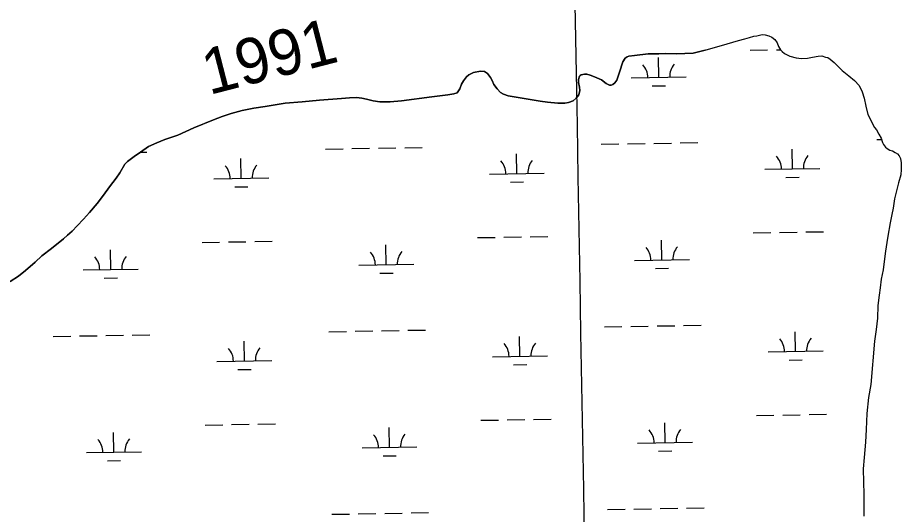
# Model space of a CAD drawing. Extents: x 3892998 to 3931244, y 278583 to 304547.
# Drawn here: x 3917313 to 3918922, y 294371 to 295276 of the extents above; entities that cross this region are included whole.
import ezdxf

# ---------------------------------------------------------------- set-up
doc = ezdxf.new("R2010")
doc.units = 0
for name, color, linetype in [('V-GRID-MAJR', 7, 'Continuous'), ('V-RIVR-IDEN', 7, 'Continuous'), ('V-TOPO-SHOR', 7, 'Continuous'), ('V-WETL-SWMP', 7, 'Continuous')]:
    doc.layers.add(name, color=color, linetype=linetype)

msp = doc.modelspace()

# ---------------------------------------------------------------- linework, layer by layer
at = {"layer": 'V-GRID-MAJR'}
msp.add_spline([(3918519.216, 284383.145), (3918413.491, 290439.973), (3918307.7120000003, 296499.886), (3918201.934, 302559.792), (3918201.88, 302562.882)], degree=3, dxfattribs=at)
at = {"layer": 'V-TOPO-SHOR'}
for points in [[(3918565.202, 295216.348), (3918605.168, 295228.228), (3918615.648, 295231.005), (3918626.123, 295234.174), (3918637.379, 295236.957), (3918645.913, 295239.724), (3918654.0640000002, 295241.712), (3918659.115, 295242.517), (3918664.1610000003, 295243.711), (3918669.205, 295244.905), (3918674.651, 295244.158), (3918680.879, 295242.638), (3918686.722, 295240.338), (3918691.799, 295235.702), (3918696.106, 295229.895), (3918698.864, 295222.916), (3918702.395, 295217.106), (3918705.133, 295214.011), (3918709.819, 295210.151), (3918719.1720000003, 295205.539), (3918730.848, 295202.493), (3918740.572, 295201.381), (3918751.451, 295201.83), (3918760.767, 295203.824), (3918770.862, 295205.82300000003), (3918777.858, 295205.862), (3918784.088, 295203.953), (3918788.757, 295202.813), (3918793.048, 295200.115), (3918800.076, 295193.93700000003), (3918807.5, 295186.982), (3918814.924, 295179.638), (3918826.6410000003, 295169.596), (3918837.182, 295161.105), (3918845.393, 295152.211), (3918851.287, 295140.58400000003), (3918854.846, 295129.332), (3918858.039, 295114.581), (3918861.6210000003, 295099.055), (3918873.8000000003, 295075.413), (3918876.934, 295071.155), (3918881.251, 295063.405), (3918885.5640000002, 295056.434), (3918888.3310000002, 295048.287), (3918889.906, 295044.797), (3918893.8200000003, 295039.767), (3918896.552, 295037.451), (3918901.622, 295034.369), (3918906.292, 295033.228), (3918911.363, 295030.148), (3918915.2600000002, 295027.838), (3918918.781, 295023.969), (3918920.753, 295018.929), (3918921.961, 295011.161), (3918922.416, 294999.115), (3918921.304, 294989.393), (3918917.1070000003, 294974.989), (3918914.0640000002, 294962.924), (3918910.273, 294945.801), (3918907.258, 294928.684), (3918905.38, 294917.012), (3918902.3540000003, 294901.839), (3918897.823, 294877.717), (3918895.9450000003, 294866.048), (3918893.312, 294850.098), (3918891.083, 294831.428), (3918889.224, 294816.261), (3918885.8200000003, 294799.142), (3918883.9620000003, 294783.583), (3918882.093, 294770.359), (3918879.866, 294751.302), (3918879.215, 294728.369), (3918876.608, 294707.756), (3918873.6180000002, 294686.362), (3918866.669, 294607.424), (3918862.9110000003, 294584.085), (3918859.575, 294554.918), (3918858.182, 294525.371), (3918857.144, 294502.434), (3918854.967, 294474.43700000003), (3918853.136, 294453.828), (3918853.269, 294429.734), (3918854.168, 294407.974), (3918854.2600000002, 294391.262), (3918854.389, 294367.941)], [(3918565.202, 295216.348), (3918543.224, 295211.107), (3918528.421, 295210.317), (3918513.0160000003, 295209.92100000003), (3918493.304, 295210.2), (3918480.9, 295210.02400000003), (3918461.6920000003, 295209.805), (3918436.4990000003, 295206.647), (3918426.302, 295205.28500000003), (3918422.909, 295204.06200000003), (3918419.519, 295201.94), (3918415.159, 295195.51), (3918409.275, 295176.264), (3918404.1610000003, 295161.726), (3918400.987, 295157.204), (3918397.304, 295154.081), (3918393.9110000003, 295152.75800000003), (3918390.909, 295152.839), (3918385.191, 295155.606), (3918376.245, 295162.354), (3918363.705, 295167.679), (3918355.98, 295171.034), (3918349.867, 295172.697), (3918345.363, 295172.76900000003), (3918339.469, 295171.632), (3918337.773, 295170.62), (3918336.282, 295169.01), (3918334.619, 295162.897), (3918334.855, 295157.29600000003), (3918336.106, 295148.89900000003), (3918336.7430000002, 295143.101), (3918334.892, 295135.186), (3918330.5270000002, 295128.956), (3918324.852, 295124.319), (3918316.169, 295121.063), (3918309.474, 295119.822), (3918297.167, 295119.746), (3918278.0470000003, 295121.728), (3918264.727, 295123.748), (3918235.682, 295128.67100000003), (3918221.16, 295131.081), (3918206.738, 295133.594), (3918198.02, 295136.14), (3918192.697, 295139.31), (3918186.254, 295145.77400000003), (3918180.4990000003, 295154.142), (3918177.1550000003, 295161.025), (3918174.3200000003, 295166.409), (3918168.8710000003, 295174.18), (3918163.247, 295177.547), (3918156.339, 295178.106), (3918143.647, 295175.924), (3918134.767, 295171.767), (3918130.69, 295168.042), (3918125.133, 295160.403), (3918121.5700000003, 295154.377), (3918118.518, 295146.056), (3918113.359, 295139.02), (3918107.67, 295136.984), (3918096.7770000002, 295135.016), (3918067.685, 295131.335), (3918012.301, 295124.389), (3917991.9050000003, 295122.363), (3917973.094, 295122.447), (3917960.677, 295124.172), (3917948.754, 295127), (3917940.1380000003, 295129.146), (3917930.225, 295130.086), (3917917.423, 295129.607), (3917903.224, 295128.218), (3917862.824, 295125.267), (3917831.524, 295122.572), (3917800.427, 295119.68), (3917764.2430000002, 295114.155), (3917743.1550000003, 295110.82300000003), (3917721.87, 295106.487), (3917701.894, 295101.263), (3917685.719, 295095.76), (3917669.65, 295089.458), (3917634.42, 295075.233), (3917604.892, 295061.443), (3917581.328, 295053.495), (3917566.457, 295047.802), (3917551.4930000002, 295040.806), (3917537.046, 295030.912), (3917525.293, 295022.533), (3917513.343, 295013.457), (3917508.3680000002, 295008.822), (3917499.162, 294993.159), (3917492.416, 294983.61100000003), (3917480.81, 294967.63300000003), (3917469.798, 294952.359), (3917457.985, 294937.378), (3917444.0810000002, 294920.684), (3917433.35, 294908.912), (3917421.9220000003, 294896.436), (3917412.673, 294887.07300000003), (3917403.818, 294879.415), (3917396.955, 294872.97000000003), (3917375.1520000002, 294855.326), (3917357.4280000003, 294841.61100000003)], [(3917357.4280000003, 294841.61100000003), (3917345.1890000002, 294830.63), (3917327.876, 294815.315), (3917315.1350000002, 294804.63), (3917299.486, 294795.33)]]:
    msp.add_lwpolyline(points, dxfattribs=at)
at = {"layer": 'V-WETL-SWMP'}
for p, q in [((3918646.9315177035, 295216.3036625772), (3918678.926724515, 295216.85750472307)), ((3918694.92432792, 295217.1344257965), (3918702.299555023, 295217.2620921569)), ((3918480.696132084, 295166.98914581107), (3918480.0730596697, 295202.9837534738)), ((3918430.703621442, 295166.12376745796), (3918530.688642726, 295167.854524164)), ((3918468.965002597, 295151.352766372), (3918492.961407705, 295151.7681479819)), ((3918018.091882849, 295038.8924044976), (3918050.0870896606, 295039.44624664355)), ((3918375.9462728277, 295045.0869212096), (3918407.9414796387, 295045.6407633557)), ((3918423.939083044, 295045.91768442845), (3918455.934289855, 295046.47152657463)), ((3918471.9318932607, 295046.74844764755), (3918503.9271000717, 295047.30228979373)), ((3918519.924703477, 295047.5792108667), (3918551.919910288, 295048.1330530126)), ((3918877.7790934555, 295053.77372757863), (3918886.4171920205, 295053.923254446)), ((3917536.5500664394, 295030.55683865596), (3917548.254269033, 295030.75944027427)), ((3917874.1134522, 295036.40011484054), (3917906.108659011, 295036.95395698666)), ((3917922.1062624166, 295037.2308780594), (3917954.1014692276, 295037.7847202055)), ((3917970.099072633, 295038.0616412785), (3918002.094279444, 295038.6154834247)), ((3918222.2556492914, 294991.6769103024), (3918221.6325768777, 295027.6715179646)), ((3918724.0884699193, 295000.3637166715), (3918723.465397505, 295036.3583243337)), ((3917720.422828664, 294982.9901039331), (3917719.79975625, 295018.9847115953)), ((3918172.2631386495, 294990.81153194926), (3918272.2481599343, 294992.54228865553)), ((3918674.0959592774, 294999.4983383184), (3918774.0809805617, 295001.2290950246)), ((3917670.4303180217, 294982.12472558), (3917770.415339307, 294983.85548228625)), ((3918210.524519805, 294976.0405308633), (3918234.520924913, 294976.455912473)), ((3918712.3573404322, 294984.7273372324), (3918736.3537455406, 294985.142718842)), ((3917708.6916991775, 294967.353724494), (3917732.6881042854, 294967.7691061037)), ((3918652.689312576, 294883.6784930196), (3918684.6845193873, 294884.2323351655)), ((3918700.682122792, 294884.50925623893), (3918732.677329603, 294885.06309838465)), ((3918748.6749330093, 294885.3400194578), (3918780.6701398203, 294885.8938616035)), ((3917649.023671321, 294866.3048802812), (3917681.018878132, 294866.85872242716)), ((3917697.016481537, 294867.13564350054), (3917729.0116883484, 294867.68948564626)), ((3917745.0092917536, 294867.96640671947), (3917777.0044985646, 294868.5202488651)), ((3918150.856491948, 294874.9916866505), (3918182.851698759, 294875.54552879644)), ((3918198.8493021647, 294875.8224498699), (3918230.844508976, 294876.37629201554)), ((3918246.842112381, 294876.65321308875), (3918278.837319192, 294877.20705523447)), ((3918486.4539269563, 294834.3639762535), (3918485.830854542, 294870.3585839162)), ((3917482.788285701, 294816.99036351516), (3917482.165213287, 294852.9849711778)), ((3917984.6211063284, 294825.67716988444), (3917983.9980339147, 294861.6717775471)), ((3918436.4614163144, 294833.4985979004), (3918536.446437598, 294835.2293546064)), ((3917432.795775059, 294816.12498516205), (3917532.780796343, 294817.855741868)), ((3917934.628595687, 294824.81179153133), (3918034.613616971, 294826.5425482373)), ((3918474.7227974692, 294818.7275968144), (3918498.7192025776, 294819.1429784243)), ((3917471.0571562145, 294801.353984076), (3917495.0535613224, 294801.76936568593)), ((3917972.889976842, 294810.04079044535), (3917996.8863819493, 294810.4561720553)), ((3917879.8712470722, 294703.77494528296), (3917911.8664538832, 294704.3287874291)), ((3917927.8640572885, 294704.6057085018), (3917959.8592640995, 294705.159550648)), ((3917975.8568675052, 294705.4364717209), (3918007.8520743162, 294705.9903138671)), ((3918023.8496777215, 294706.2672349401), (3918055.844884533, 294706.821077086)), ((3918381.7040677, 294712.461751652), (3918413.699274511, 294713.0155937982)), ((3918429.6968779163, 294713.2925148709), (3918461.6920847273, 294713.84635701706)), ((3918477.689688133, 294714.12327809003), (3918509.6848949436, 294714.67712023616)), ((3918525.6824983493, 294714.95404130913), (3918557.6777051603, 294715.507883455)), ((3918729.8462647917, 294667.7385471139), (3918729.223192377, 294703.7331547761)), ((3917378.038426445, 294695.0881389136), (3917410.033633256, 294695.6419810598)), ((3917426.031236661, 294695.91890213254), (3917458.026443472, 294696.47274427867)), ((3917474.024046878, 294696.74966535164), (3917506.019253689, 294697.30350749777)), ((3917522.0168570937, 294697.58042857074), (3917554.012063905, 294698.1342707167)), ((3917726.180623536, 294650.3649343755), (3917725.5575511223, 294686.3595420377)), ((3918228.013444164, 294659.05174074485), (3918227.39037175, 294695.04634840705)), ((3918178.020933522, 294658.18636239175), (3918278.005954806, 294659.91711909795)), ((3918679.8537541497, 294666.8731687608), (3918779.838775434, 294668.603925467)), ((3917676.188112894, 294649.4995560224), (3917776.1731341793, 294651.2303127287)), ((3918216.2823146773, 294643.4153613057), (3918240.278719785, 294643.8307429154)), ((3918718.1151353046, 294652.1021676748), (3918742.111540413, 294652.51754928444)), ((3917714.4494940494, 294634.7285549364), (3917738.445899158, 294635.1439365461)), ((3918156.6142868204, 294542.366517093), (3918188.609493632, 294542.92035923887)), ((3918204.6070970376, 294543.1972803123), (3918236.602303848, 294543.75112245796)), ((3918252.599907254, 294544.0280435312), (3918284.595114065, 294544.5818856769)), ((3918658.4471074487, 294551.053323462), (3918690.4423142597, 294551.6071656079)), ((3918706.4399176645, 294551.88408668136), (3918738.435124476, 294552.4379288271)), ((3918754.4327278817, 294552.7148499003), (3918786.4279346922, 294553.26869204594)), ((3917654.7814661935, 294533.67971072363), (3917686.776673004, 294534.2335528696)), ((3917702.7742764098, 294534.510473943), (3917734.769483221, 294535.0643160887)), ((3917750.767086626, 294535.3412371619), (3917782.762293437, 294535.89507930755)), ((3917990.3789012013, 294493.05200032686), (3917989.755828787, 294529.0466079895)), ((3918492.2117218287, 294501.73880669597), (3918491.5886494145, 294537.73341435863)), ((3917488.5460805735, 294484.3651939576), (3917487.9230081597, 294520.35980162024)), ((3917940.3863905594, 294492.18662197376), (3918040.371411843, 294493.91737867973)), ((3918442.2192111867, 294500.8734283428), (3918542.2042324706, 294502.60418504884)), ((3917438.553569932, 294483.4998156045), (3917538.538591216, 294485.23057231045)), ((3917978.6477717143, 294477.41562088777), (3918002.644176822, 294477.8310024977)), ((3918480.480592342, 294486.1024272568), (3918504.47699745, 294486.51780886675)), ((3917476.814951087, 294468.7288145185), (3917500.811356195, 294469.14419612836)), ((3918387.461862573, 294379.83658209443), (3918419.457069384, 294380.3904242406)), ((3918435.4546727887, 294380.6673453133), (3918467.4498795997, 294381.2211874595)), ((3918483.4474830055, 294381.49810853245), (3918515.4426898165, 294382.0519506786)), ((3918531.4402932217, 294382.32887175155), (3918563.435500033, 294382.88271389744)), ((3917885.6290419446, 294371.1497757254), (3917917.6242487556, 294371.7036178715)), ((3917933.6218521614, 294371.98053894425), (3917965.6170589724, 294372.53438109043)), ((3917981.6146623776, 294372.81130216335), (3918013.609869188, 294373.36514430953)), ((3918029.6074725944, 294373.6420653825), (3918061.6026794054, 294374.1959075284))]:
    msp.add_line(p, q, dxfattribs=at)
for points in [[(3918390.909, 295152.84), (3918393.9110000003, 295152.75800000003), (3918397.305, 295154.08), (3918400.987, 295157.204), (3918404.1610000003, 295161.726), (3918409.274, 295176.265), (3918415.1580000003, 295195.51), (3918419.52, 295201.94), (3918422.909, 295204.06200000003), (3918426.3030000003, 295205.284), (3918436.4990000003, 295206.647), (3918461.6920000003, 295209.804), (3918480.9, 295210.023), (3918493.305, 295210.2), (3918513.0160000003, 295209.92100000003), (3918528.421, 295210.317), (3918543.224, 295211.108), (3918565.202, 295216.347), (3918605.169, 295228.228), (3918615.647, 295231.006), (3918626.123, 295234.173), (3918637.379, 295236.956), (3918645.914, 295239.724), (3918654.065, 295241.712), (3918659.114, 295242.517), (3918664.16, 295243.711), (3918669.2060000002, 295244.905), (3918674.651, 295244.158), (3918680.878, 295242.638), (3918686.721, 295240.338), (3918691.799, 295235.702), (3918696.106, 295229.896), (3918698.865, 295222.915), (3918702.395, 295217.105), (3918705.133, 295214.011), (3918709.818, 295210.15), (3918719.1720000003, 295205.538), (3918730.848, 295202.493), (3918740.571, 295201.381), (3918751.451, 295201.829), (3918760.768, 295203.824), (3918770.862, 295205.82300000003), (3918777.858, 295205.862), (3918784.0870000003, 295203.953), (3918788.757, 295202.813), (3918793.0470000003, 295200.116), (3918800.077, 295193.936), (3918807.5, 295186.981), (3918814.9250000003, 295179.638), (3918826.6410000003, 295169.597), (3918837.182, 295161.105), (3918845.393, 295152.211), (3918851.287, 295140.58400000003), (3918854.847, 295129.332), (3918858.038, 295114.581), (3918861.6210000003, 295099.054), (3918873.8000000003, 295075.413), (3918876.933, 295071.155), (3918881.251, 295063.406), (3918885.565, 295056.433), (3918888.3310000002, 295048.287), (3918889.9050000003, 295044.798), (3918893.819, 295039.767), (3918896.552, 295037.45), (3918901.622, 295034.368), (3918906.292, 295033.228), (3918911.362, 295030.147), (3918915.261, 295027.837), (3918918.781, 295023.969), (3918920.752, 295018.928), (3918921.961, 295011.161), (3918922.416, 294999.115), (3918921.304, 294989.392), (3918917.108, 294974.989), (3918914.065, 294962.924), (3918910.273, 294945.801), (3918907.258, 294928.684), (3918905.38, 294917.013), (3918902.3540000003, 294901.839), (3918897.823, 294877.717), (3918895.9450000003, 294866.047), (3918893.312, 294850.097), (3918891.083, 294831.429), (3918889.224, 294816.261), (3918885.8200000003, 294799.141), (3918883.963, 294783.58400000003), (3918882.093, 294770.359), (3918879.866, 294751.303), (3918879.215, 294728.368), (3918876.609, 294707.755), (3918873.6180000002, 294686.362), (3918866.669, 294607.425), (3918862.9110000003, 294584.085), (3918859.574, 294554.917), (3918858.183, 294525.371), (3918857.144, 294502.434), (3918854.966, 294474.438), (3918853.137, 294453.829), (3918853.27, 294429.733), (3918854.168, 294407.973), (3918854.2600000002, 294391.261)], [(3917299.486, 294795.33), (3917315.136, 294804.631), (3917327.876, 294815.315), (3917345.19, 294830.629), (3917357.4280000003, 294841.61), (3917375.1520000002, 294855.326), (3917396.954, 294872.969), (3917403.8170000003, 294879.415), (3917412.674, 294887.07300000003), (3917421.921, 294896.435), (3917433.35, 294908.912), (3917444.082, 294920.684), (3917457.986, 294937.377), (3917469.799, 294952.358), (3917480.81, 294967.63300000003), (3917492.417, 294983.612), (3917499.162, 294993.159), (3917508.369, 295008.82300000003), (3917513.343, 295013.456), (3917525.293, 295022.534), (3917537.0470000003, 295030.911), (3917551.4930000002, 295040.805), (3917566.457, 295047.801), (3917581.329, 295053.495), (3917604.892, 295061.444), (3917634.421, 295075.233), (3917669.65, 295089.458), (3917685.719, 295095.76), (3917701.893, 295101.262), (3917721.87, 295106.488), (3917743.154, 295110.822), (3917764.244, 295114.154), (3917800.427, 295119.68), (3917831.524, 295122.57300000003), (3917862.823, 295125.267), (3917903.224, 295128.218), (3917917.423, 295129.606), (3917930.2260000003, 295130.086), (3917940.137, 295129.146), (3917948.754, 295126.999), (3917960.677, 295124.17100000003), (3917973.094, 295122.447), (3917991.904, 295122.363), (3918012.301, 295124.389), (3918067.685, 295131.335), (3918096.776, 295135.016), (3918107.67, 295136.984), (3918113.36, 295139.02), (3918118.519, 295146.056), (3918121.569, 295154.378), (3918125.134, 295160.403), (3918130.6890000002, 295168.041), (3918134.768, 295171.768), (3918143.647, 295175.925), (3918156.339, 295178.105), (3918163.2460000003, 295177.547), (3918168.87, 295174.18), (3918174.3200000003, 295166.41000000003), (3918177.1550000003, 295161.025), (3918180.4990000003, 295154.142), (3918186.254, 295145.773), (3918192.697, 295139.31), (3918198.019, 295136.141), (3918206.739, 295133.594), (3918221.1610000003, 295131.082), (3918235.683, 295128.67), (3918264.728, 295123.74700000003), (3918278.0470000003, 295121.728), (3918297.168, 295119.745), (3918309.474, 295119.821), (3918316.169, 295121.063), (3918324.853, 295124.318), (3918330.5270000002, 295128.956), (3918334.8910000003, 295135.186), (3918336.7430000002, 295143.101), (3918336.1070000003, 295148.9), (3918334.855, 295157.29600000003), (3918334.62, 295162.897), (3918336.2830000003, 295169.011), (3918337.774, 295170.621), (3918339.468, 295171.632), (3918345.364, 295172.76900000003), (3918349.867, 295172.696), (3918355.98, 295171.033), (3918363.705, 295167.679), (3918376.244, 295162.354), (3918385.19, 295155.606), (3918390.909, 295152.84)], [(3918854.2600000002, 294391.261), (3918854.389, 294367.942)]]:
    msp.add_lwpolyline(points, dxfattribs=at)
for centre, radius, start, end in [((3918425.4532529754, 295166.5077570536), 35.24628790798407, 0.21988000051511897, 41.76353833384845), ((3918535.9225758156, 295168.4199986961), 35.246287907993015, 140.21987699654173, 181.76353532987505), ((3918668.845590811, 294999.8823279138), 35.24628790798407, 0.21988000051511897, 41.76353833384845), ((3918779.3149136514, 295001.7945695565), 35.246287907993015, 140.21987699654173, 181.76353532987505), ((3918167.012770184, 294991.1955215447), 35.24628790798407, 0.21988000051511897, 41.76353833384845), ((3918277.482093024, 294993.10776318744), 35.246287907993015, 140.21987699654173, 181.76353532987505), ((3917665.1799495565, 294982.5087151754), 35.24628790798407, 0.21988000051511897, 41.76353833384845), ((3917775.649272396, 294984.4209568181), 35.246287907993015, 140.21987699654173, 181.76353532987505), ((3917929.37822722, 294825.19578112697), 35.24628790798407, 0.21988000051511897, 41.76353833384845), ((3918039.84755006, 294827.10802276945), 35.246287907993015, 140.21987699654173, 181.76353532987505), ((3918431.2110478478, 294833.8825874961), 35.24628790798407, 0.21988000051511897, 41.76353833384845), ((3918541.680370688, 294835.7948291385), 35.246287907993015, 140.21987699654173, 181.76353532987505), ((3917427.5454065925, 294816.5089747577), 35.24628790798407, 0.21988000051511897, 41.76353833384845), ((3917538.014729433, 294818.42121640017), 35.246287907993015, 140.21987699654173, 181.76353532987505), ((3918674.6033856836, 294667.2571583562), 35.24628790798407, 0.21988000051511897, 41.76353833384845), ((3918785.072708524, 294669.1693999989), 35.246287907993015, 140.21987699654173, 181.76353532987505), ((3917670.937744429, 294649.8835456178), 35.24628790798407, 0.21988000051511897, 41.76353833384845), ((3917781.4070672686, 294651.7957872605), 35.246287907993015, 140.21987699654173, 181.76353532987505), ((3918172.770565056, 294658.57035198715), 35.24628790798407, 0.21988000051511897, 41.76353833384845), ((3918283.239887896, 294660.48259362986), 35.246287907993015, 140.21987699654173, 181.76353532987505), ((3918436.96884272, 294501.2574179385), 35.24628790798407, 0.21988000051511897, 41.76353833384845), ((3918547.438165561, 294503.169659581), 35.246287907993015, 140.21987699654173, 181.76353532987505), ((3917935.136022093, 294492.5706115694), 35.24628790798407, 0.21988000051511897, 41.76353833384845), ((3918045.6053449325, 294494.48285321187), 35.246287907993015, 140.21987699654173, 181.76353532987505), ((3917433.3032014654, 294483.8838052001), 35.24628790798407, 0.21988000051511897, 41.76353833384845), ((3917543.7725243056, 294485.7960468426), 35.246287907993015, 140.21987699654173, 181.76353532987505)]:
    msp.add_arc(centre, radius, start, end, dxfattribs=at)

# ---------------------------------------------------------------- texts
at = {"layer": 'V-RIVR-IDEN'}
msp.add_text('1991', height=82.99983200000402, rotation=14.462371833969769, dxfattribs=at).set_placement((3917661.870799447, 295134.56391489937))

doc.saveas('drawing.dxf')
